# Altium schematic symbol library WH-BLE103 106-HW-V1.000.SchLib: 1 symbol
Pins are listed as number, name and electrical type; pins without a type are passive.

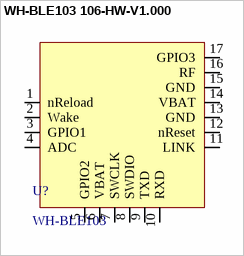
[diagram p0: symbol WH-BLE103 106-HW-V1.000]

## WH-BLE103 106-HW-V1.000
designator U?, comment WH-BLE103
pins: 1 nReload, 2 Wake, 3 GPIO1, 4 ADC, 5 GPIO2, 6 VBAT, 7 SWCLK, 8 SWDIO, 9 TXD, 10 RXD, 11 LINK, 12 nReset, 13 GND, 14 VBAT, 15 GND, 16 RF, 17 GPIO3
